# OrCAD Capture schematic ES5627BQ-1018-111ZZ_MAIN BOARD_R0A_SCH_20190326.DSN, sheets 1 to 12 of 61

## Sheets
1 P001_Revision History: rev: R0A
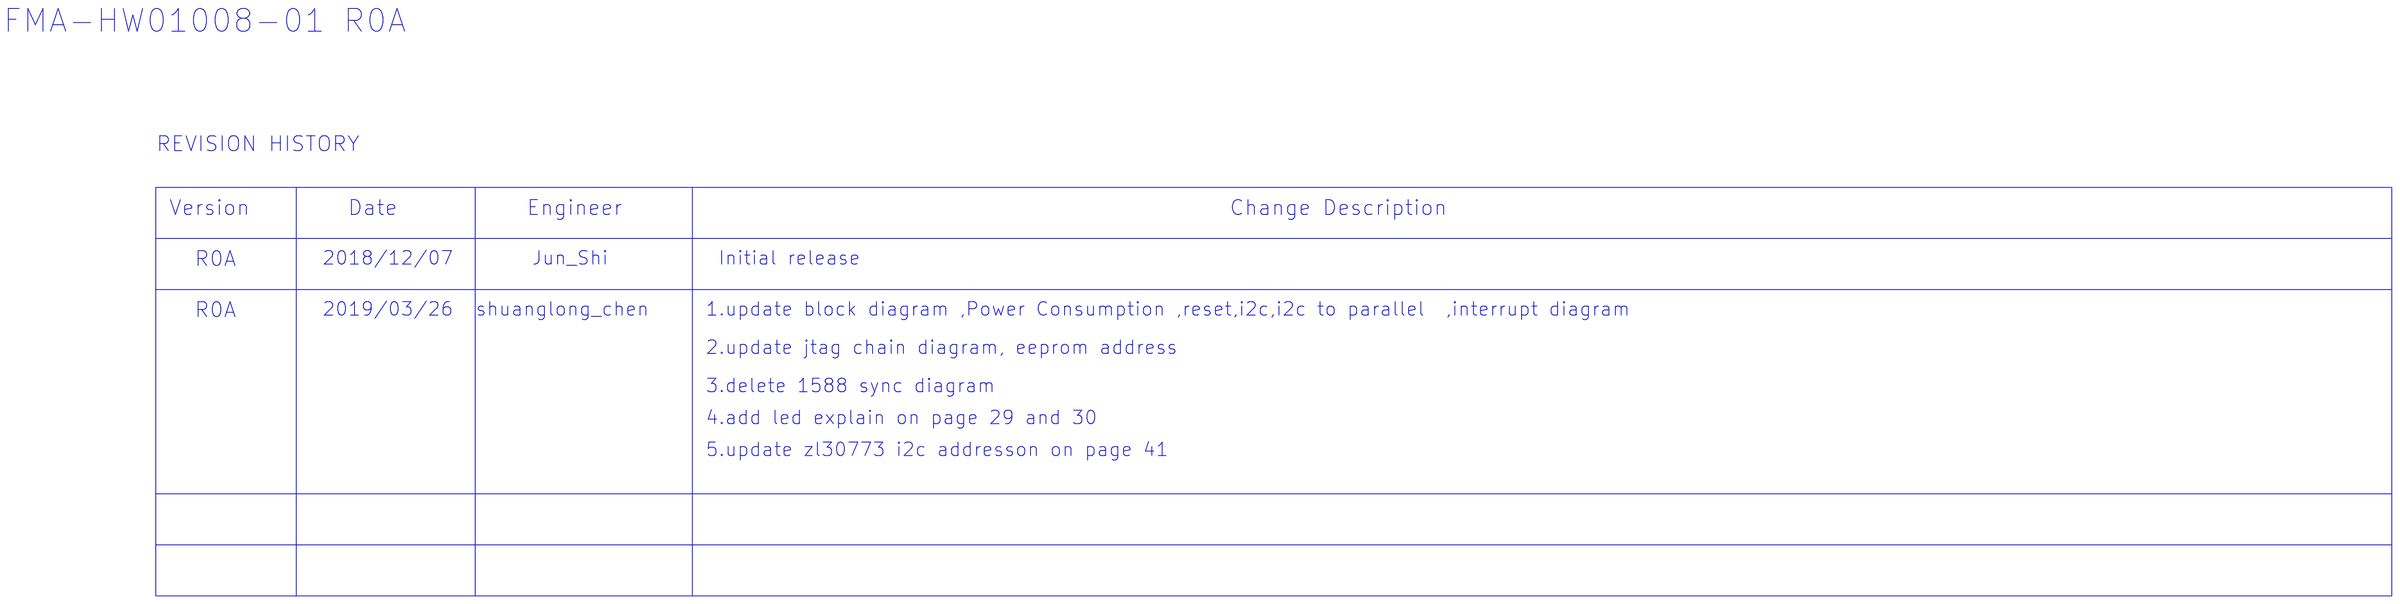
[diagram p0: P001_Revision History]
2 P002_Index List
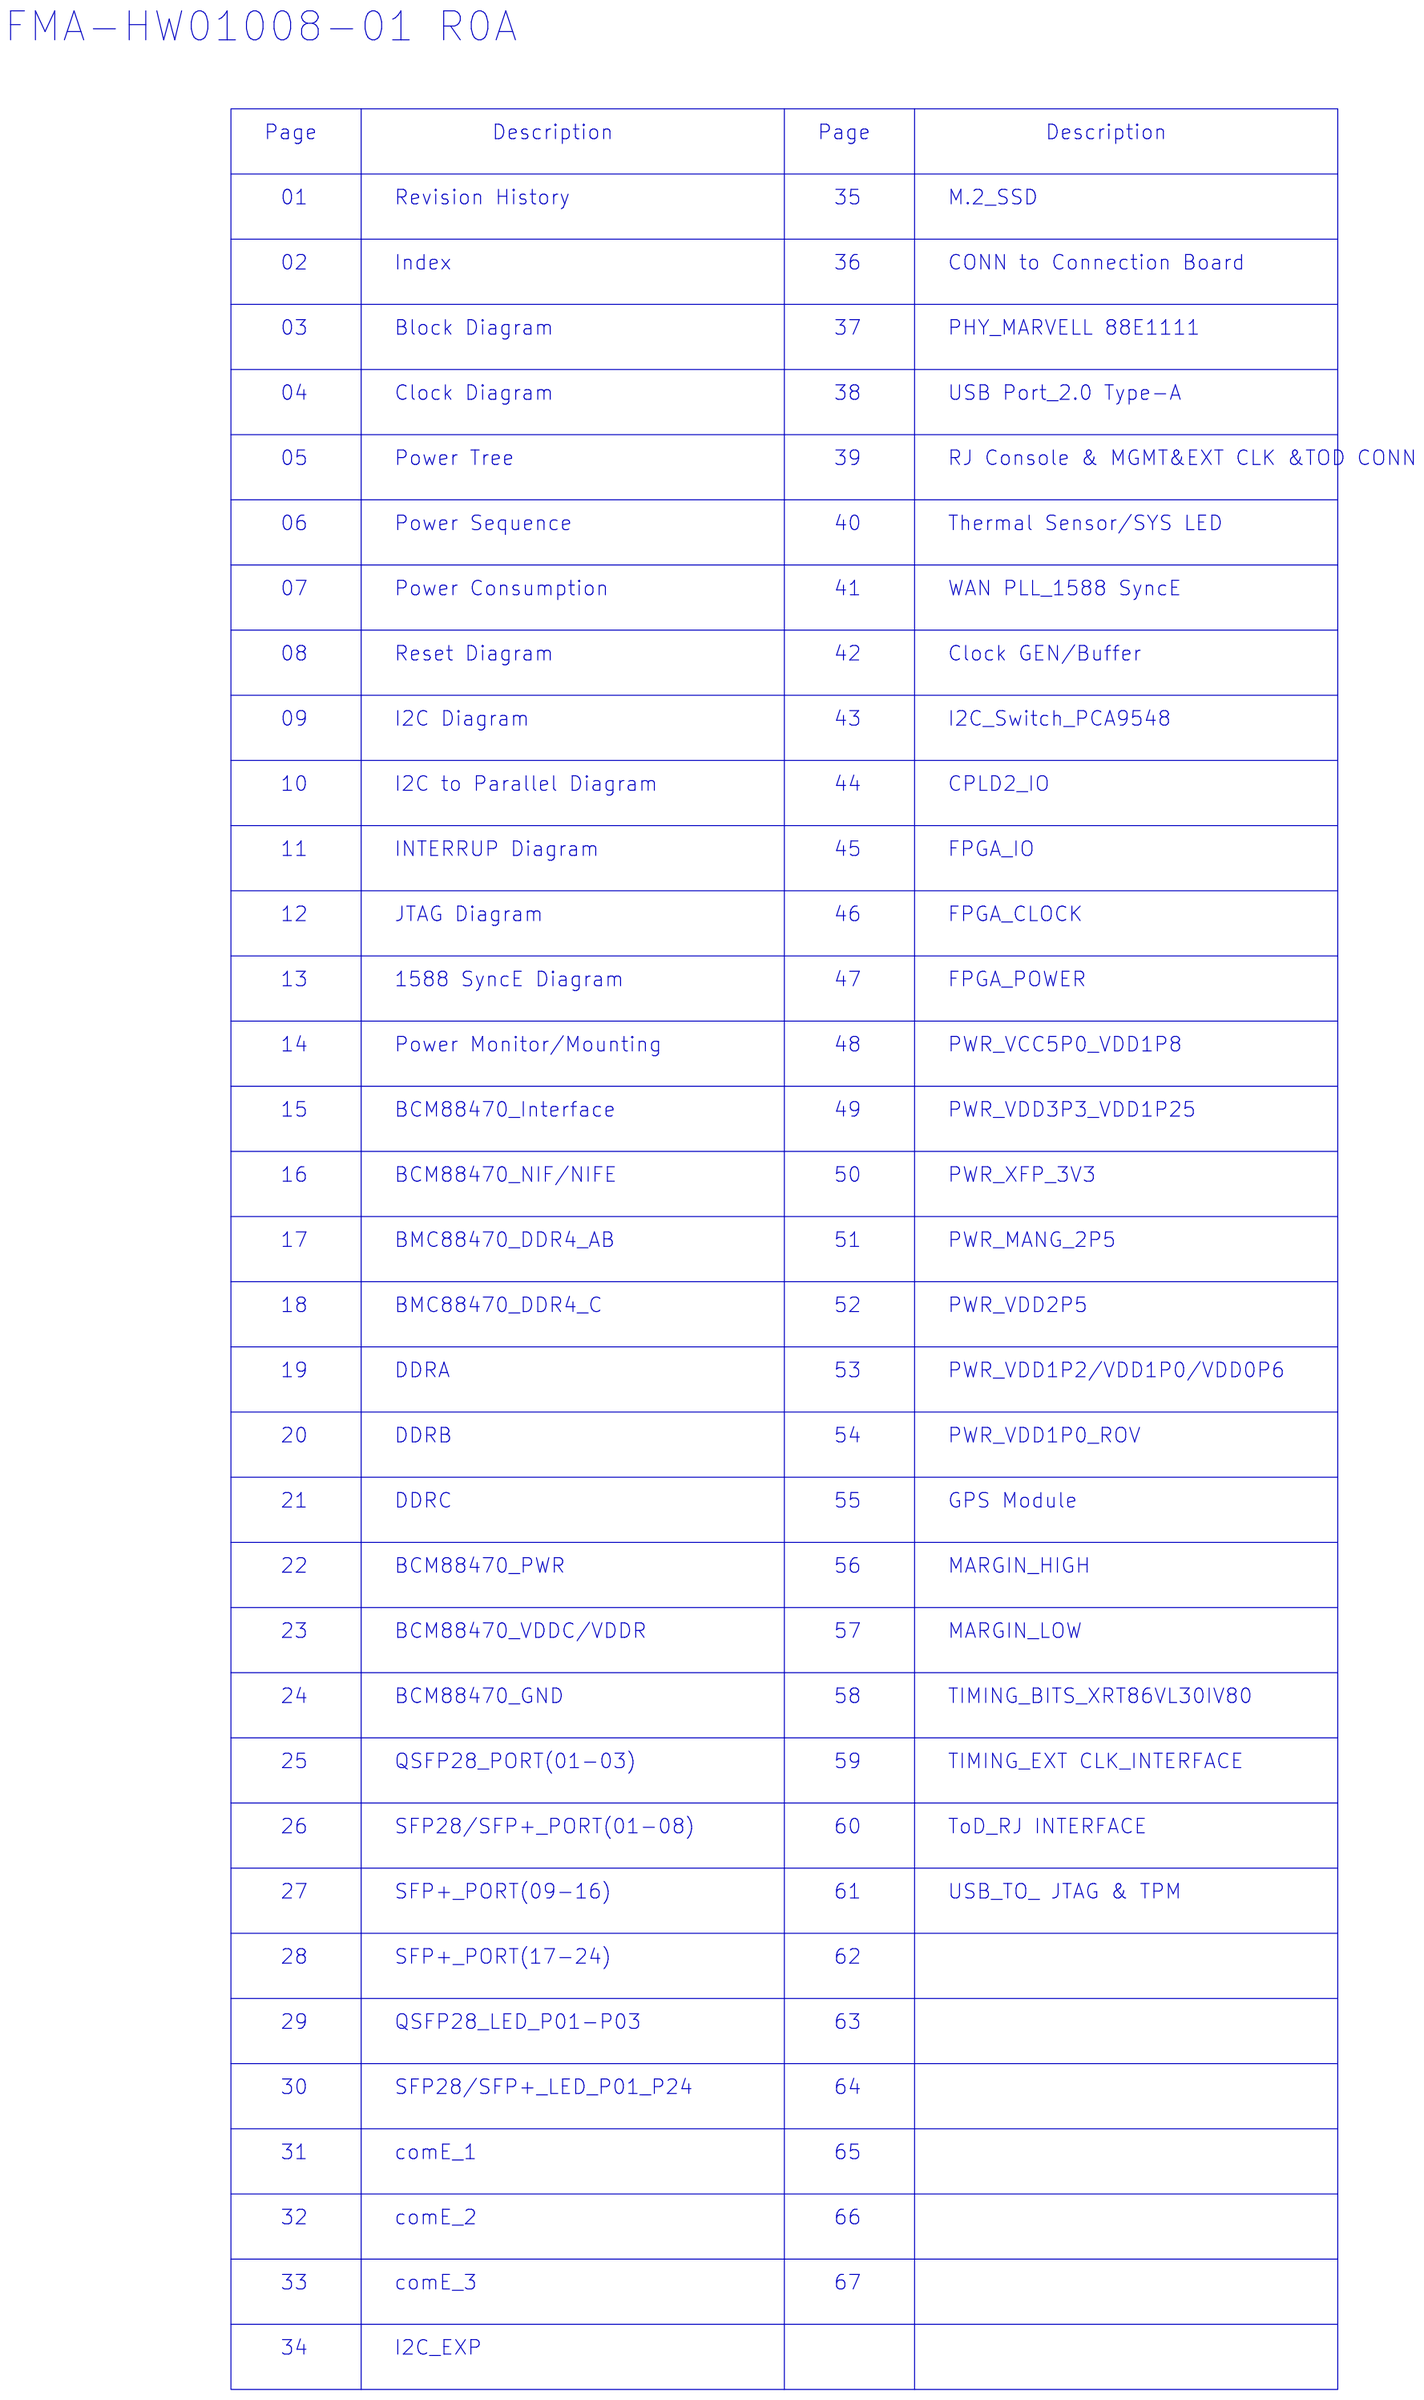
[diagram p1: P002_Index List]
3 P003_Block Diagram
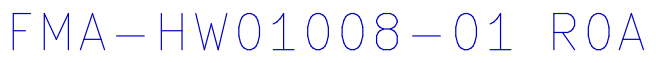
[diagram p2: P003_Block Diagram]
4 P004_Clock Diagram
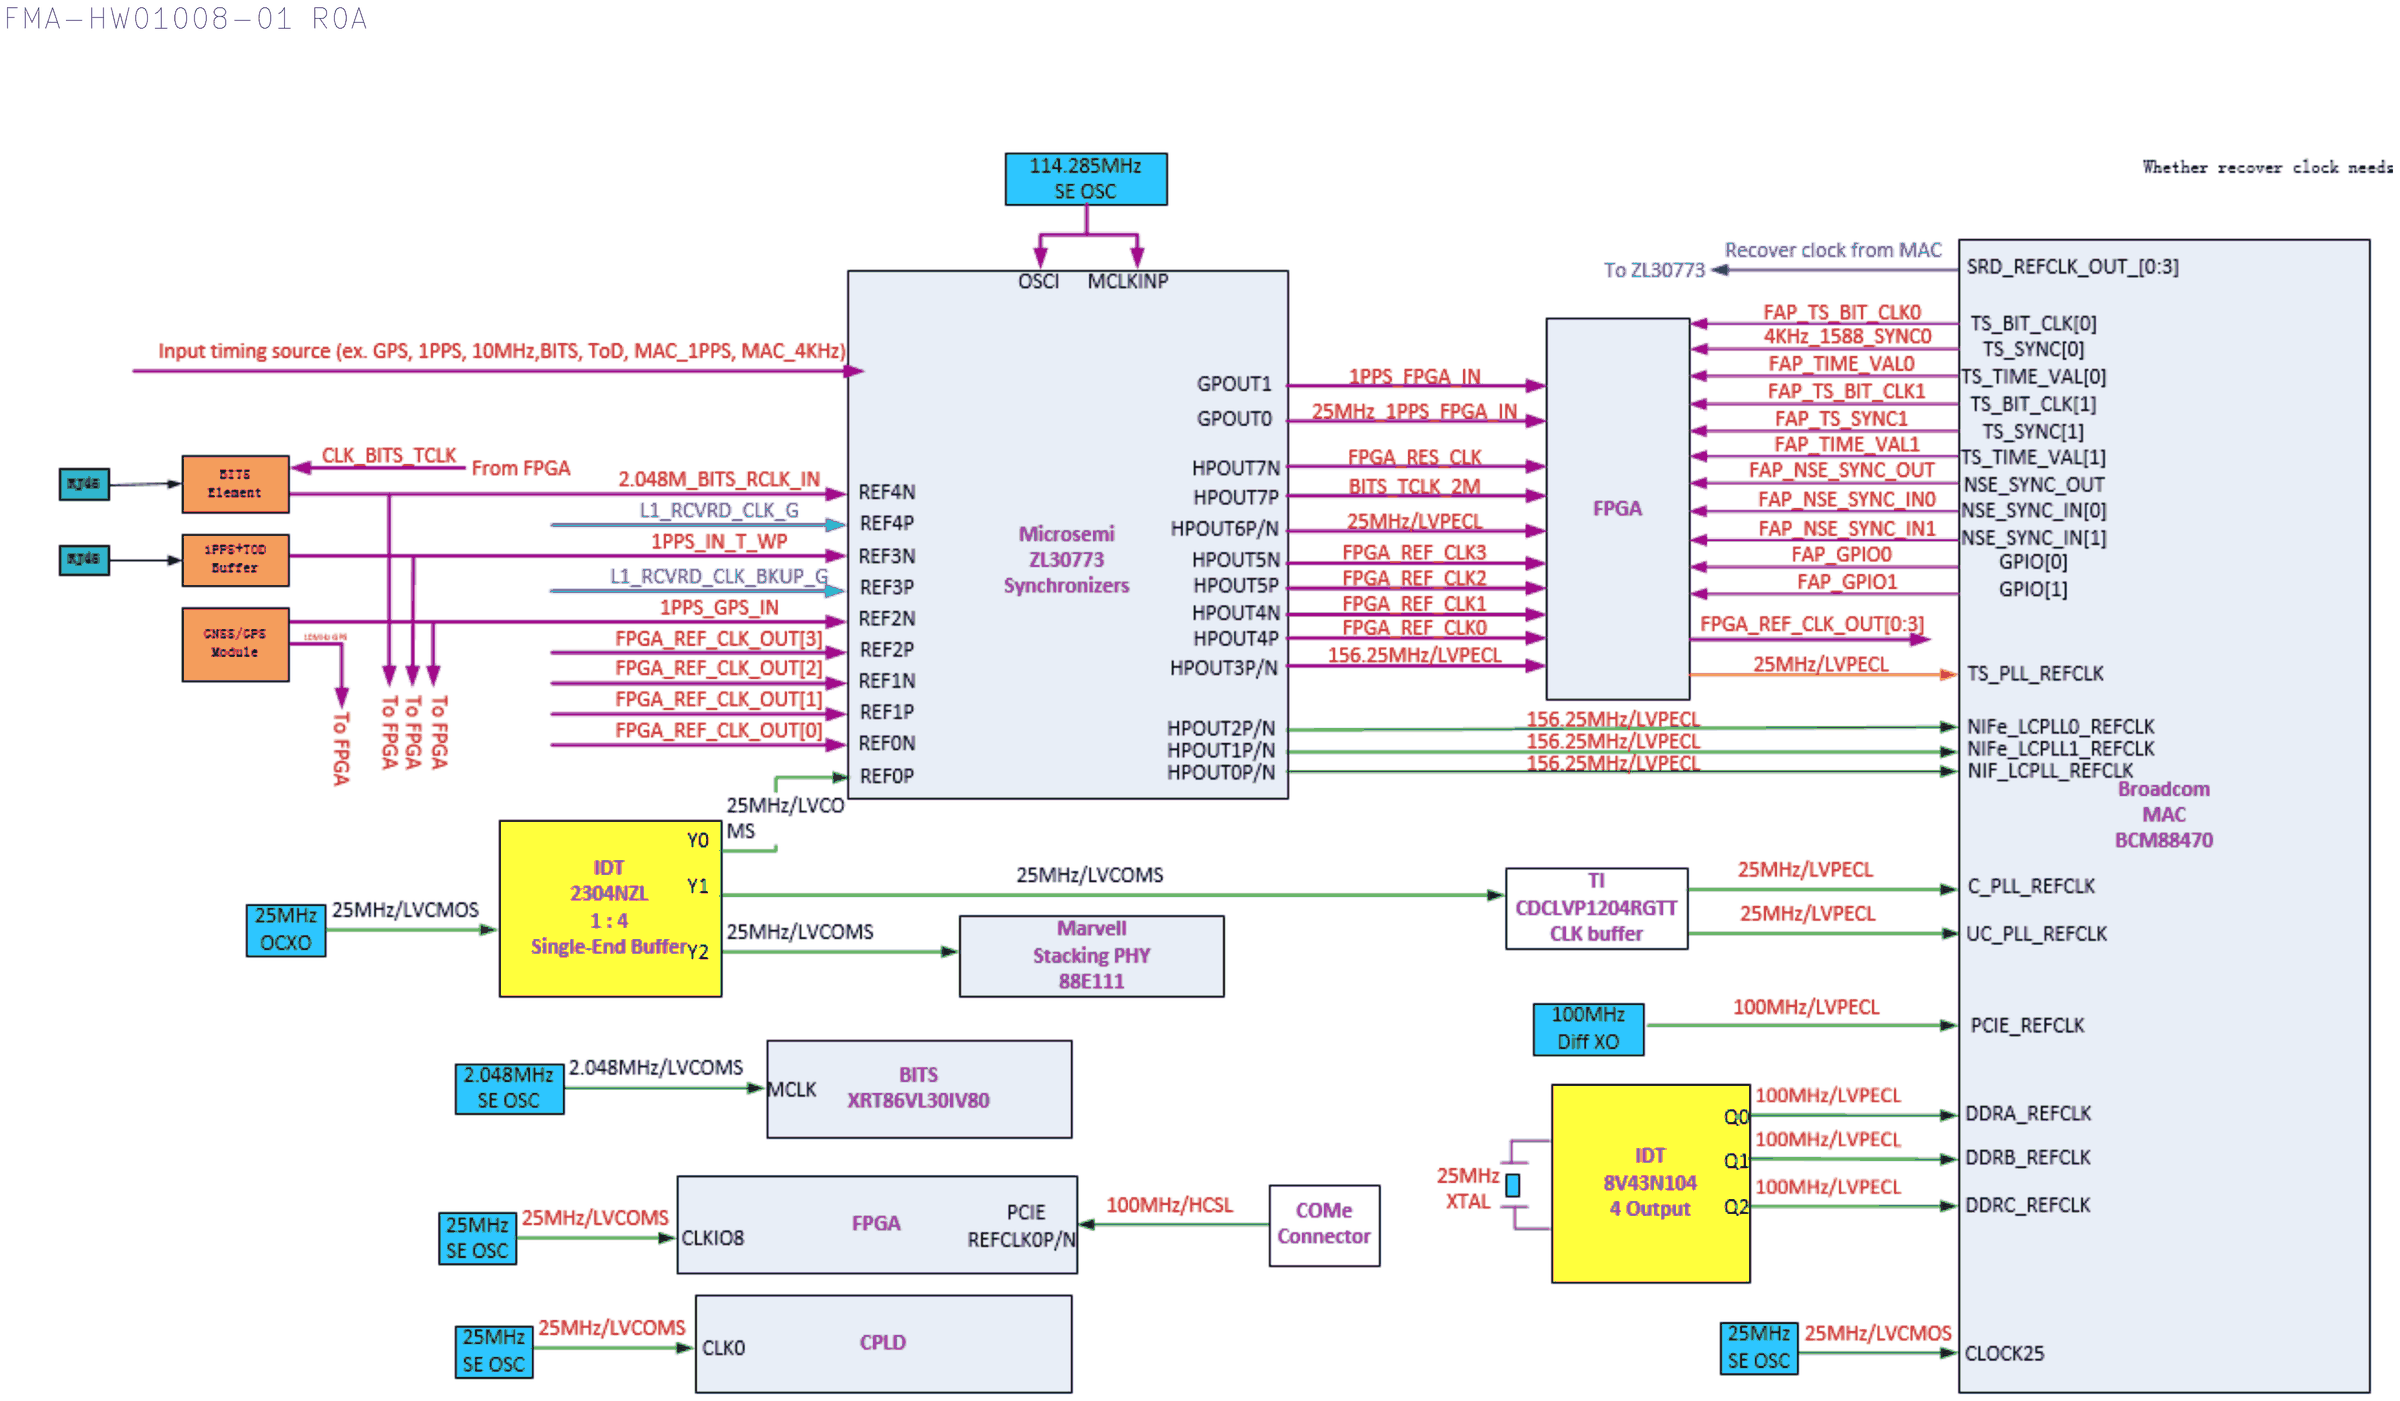
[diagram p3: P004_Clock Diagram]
5 P005_Power Tree
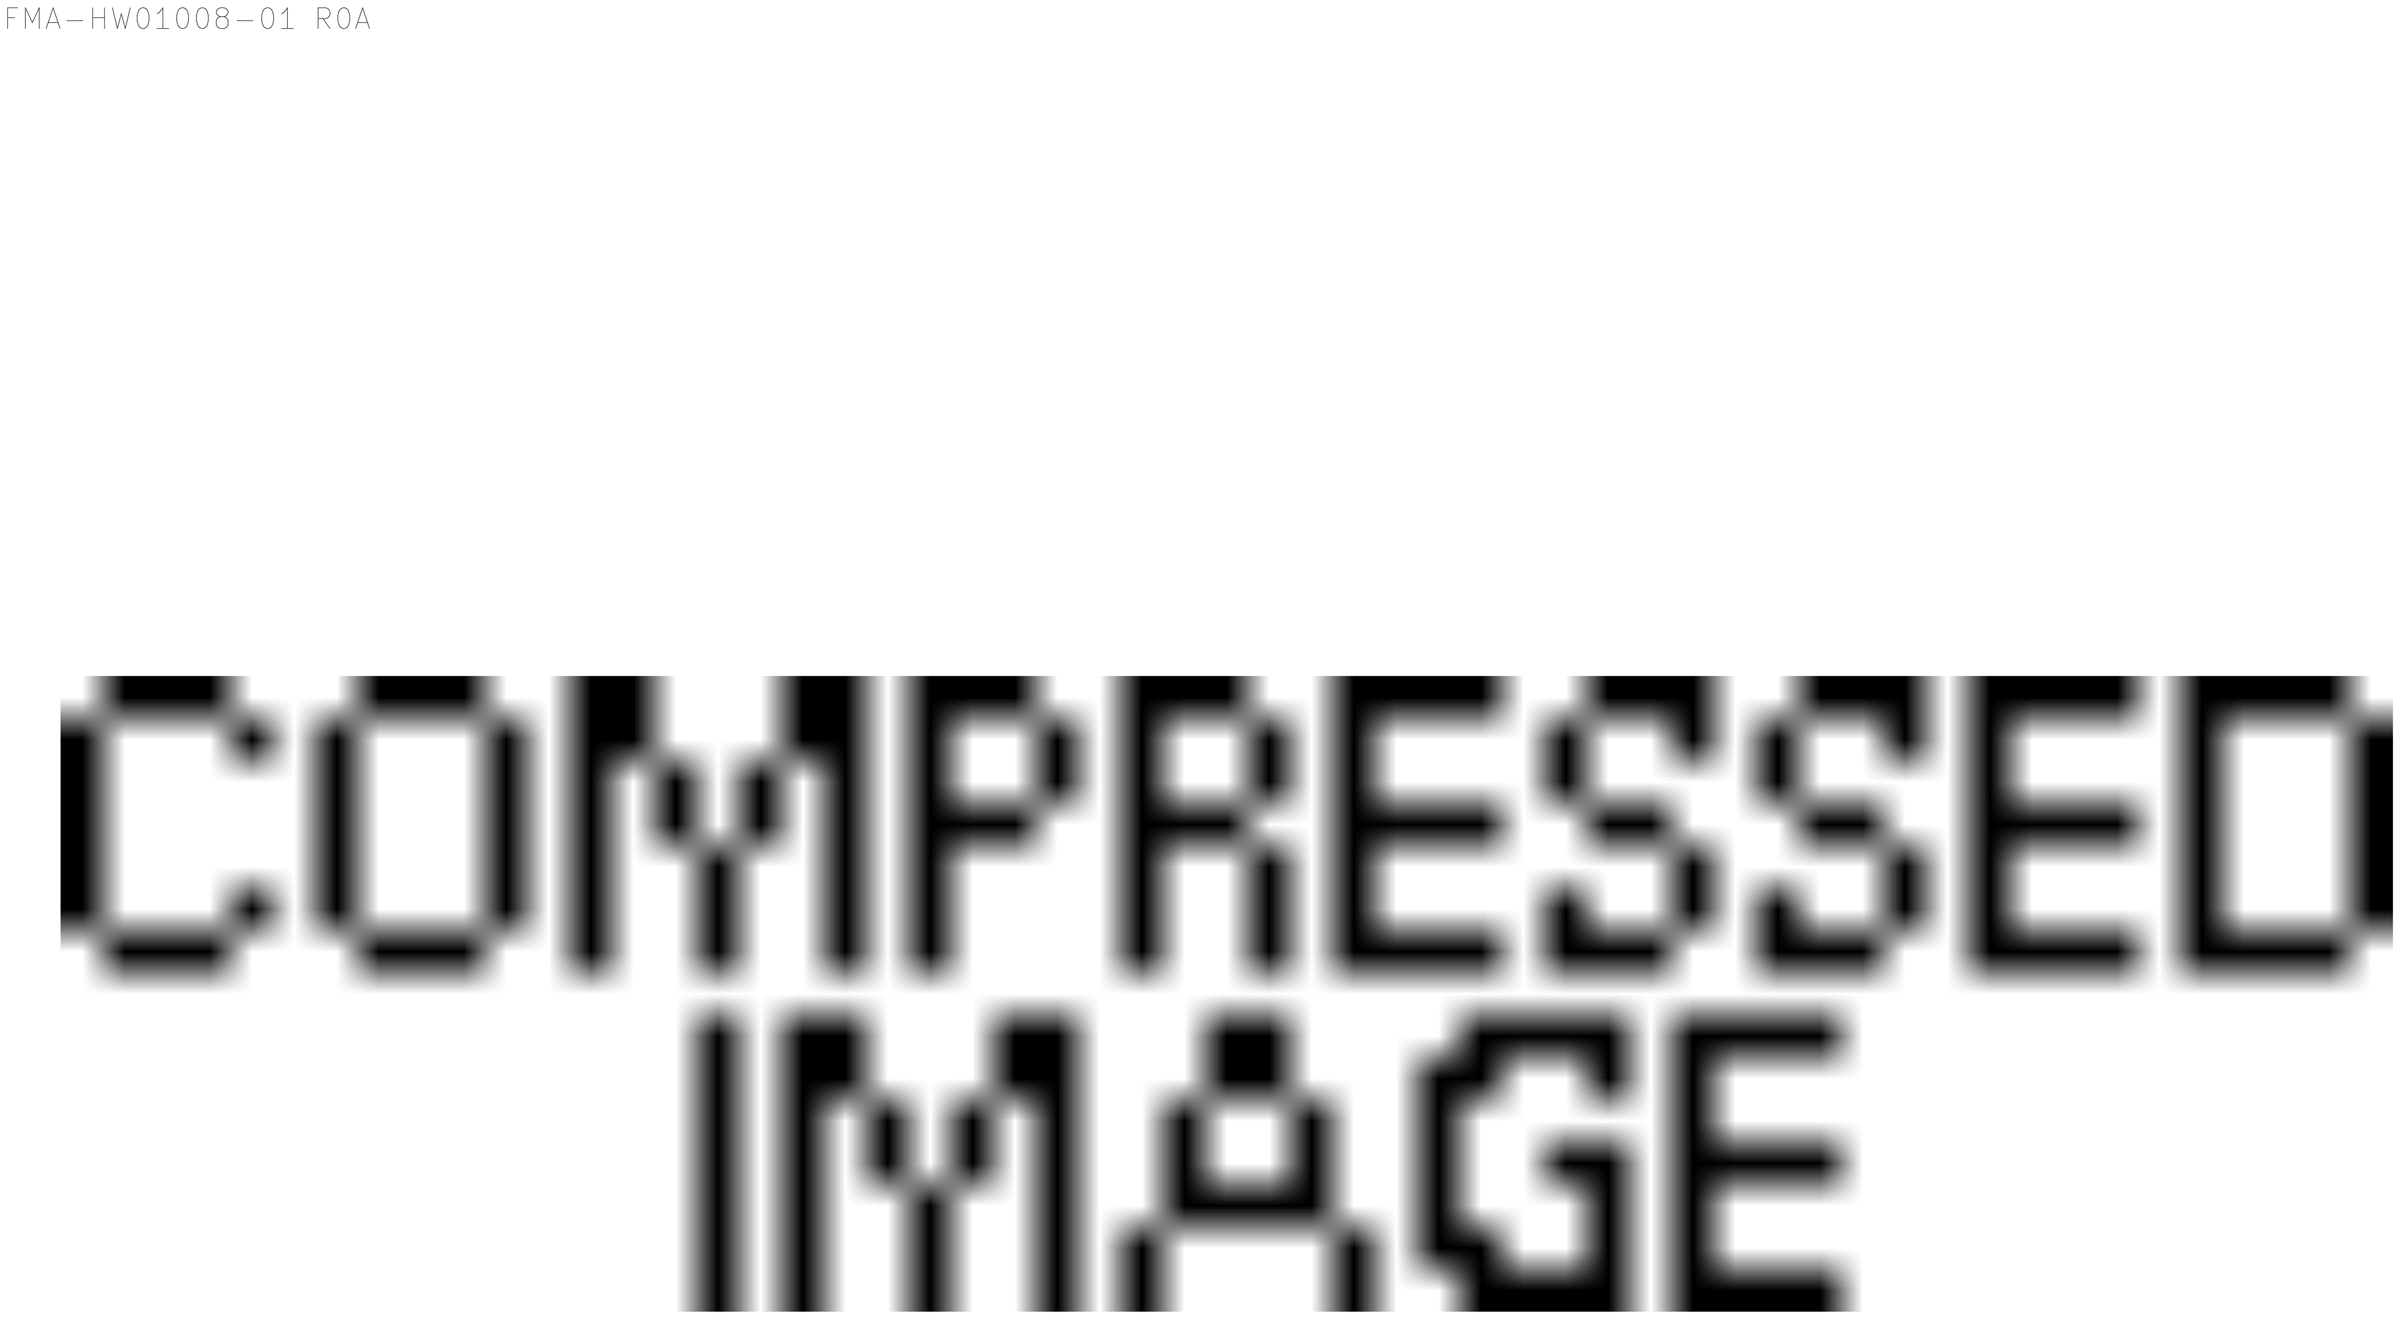
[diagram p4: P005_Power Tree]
6 P006_Power Sequence
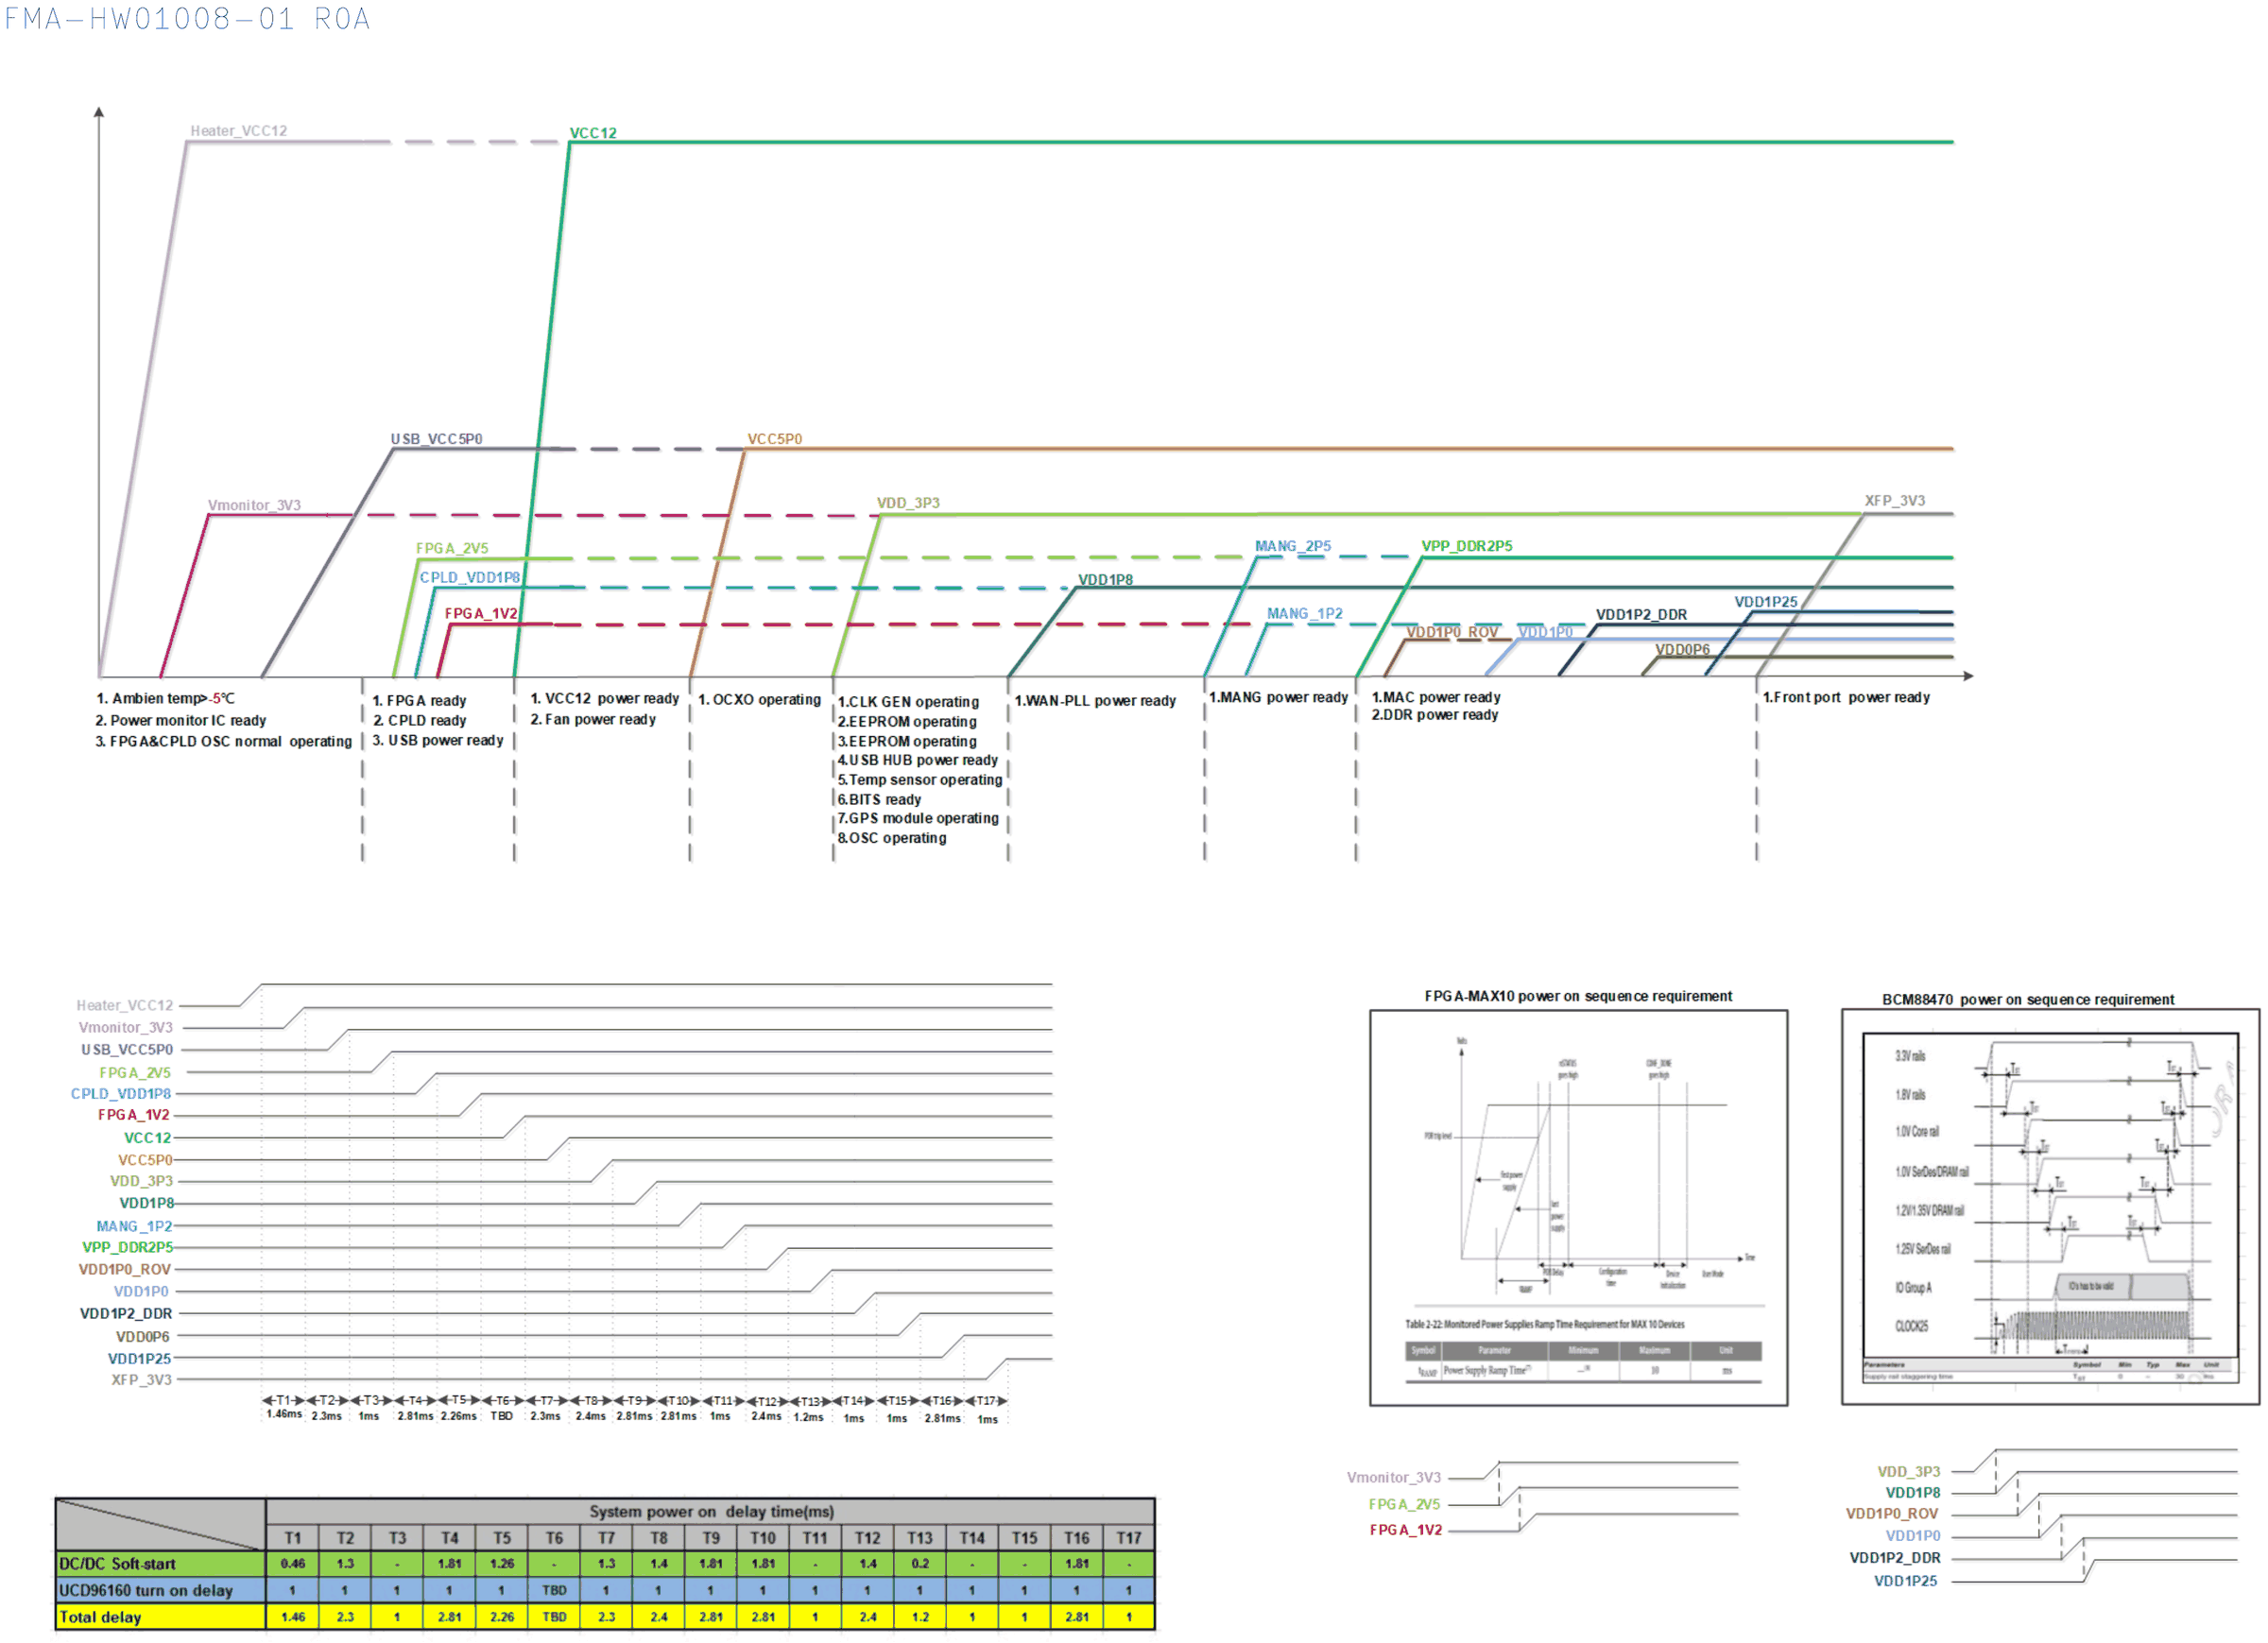
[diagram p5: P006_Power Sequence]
7 P007_Power Consumption
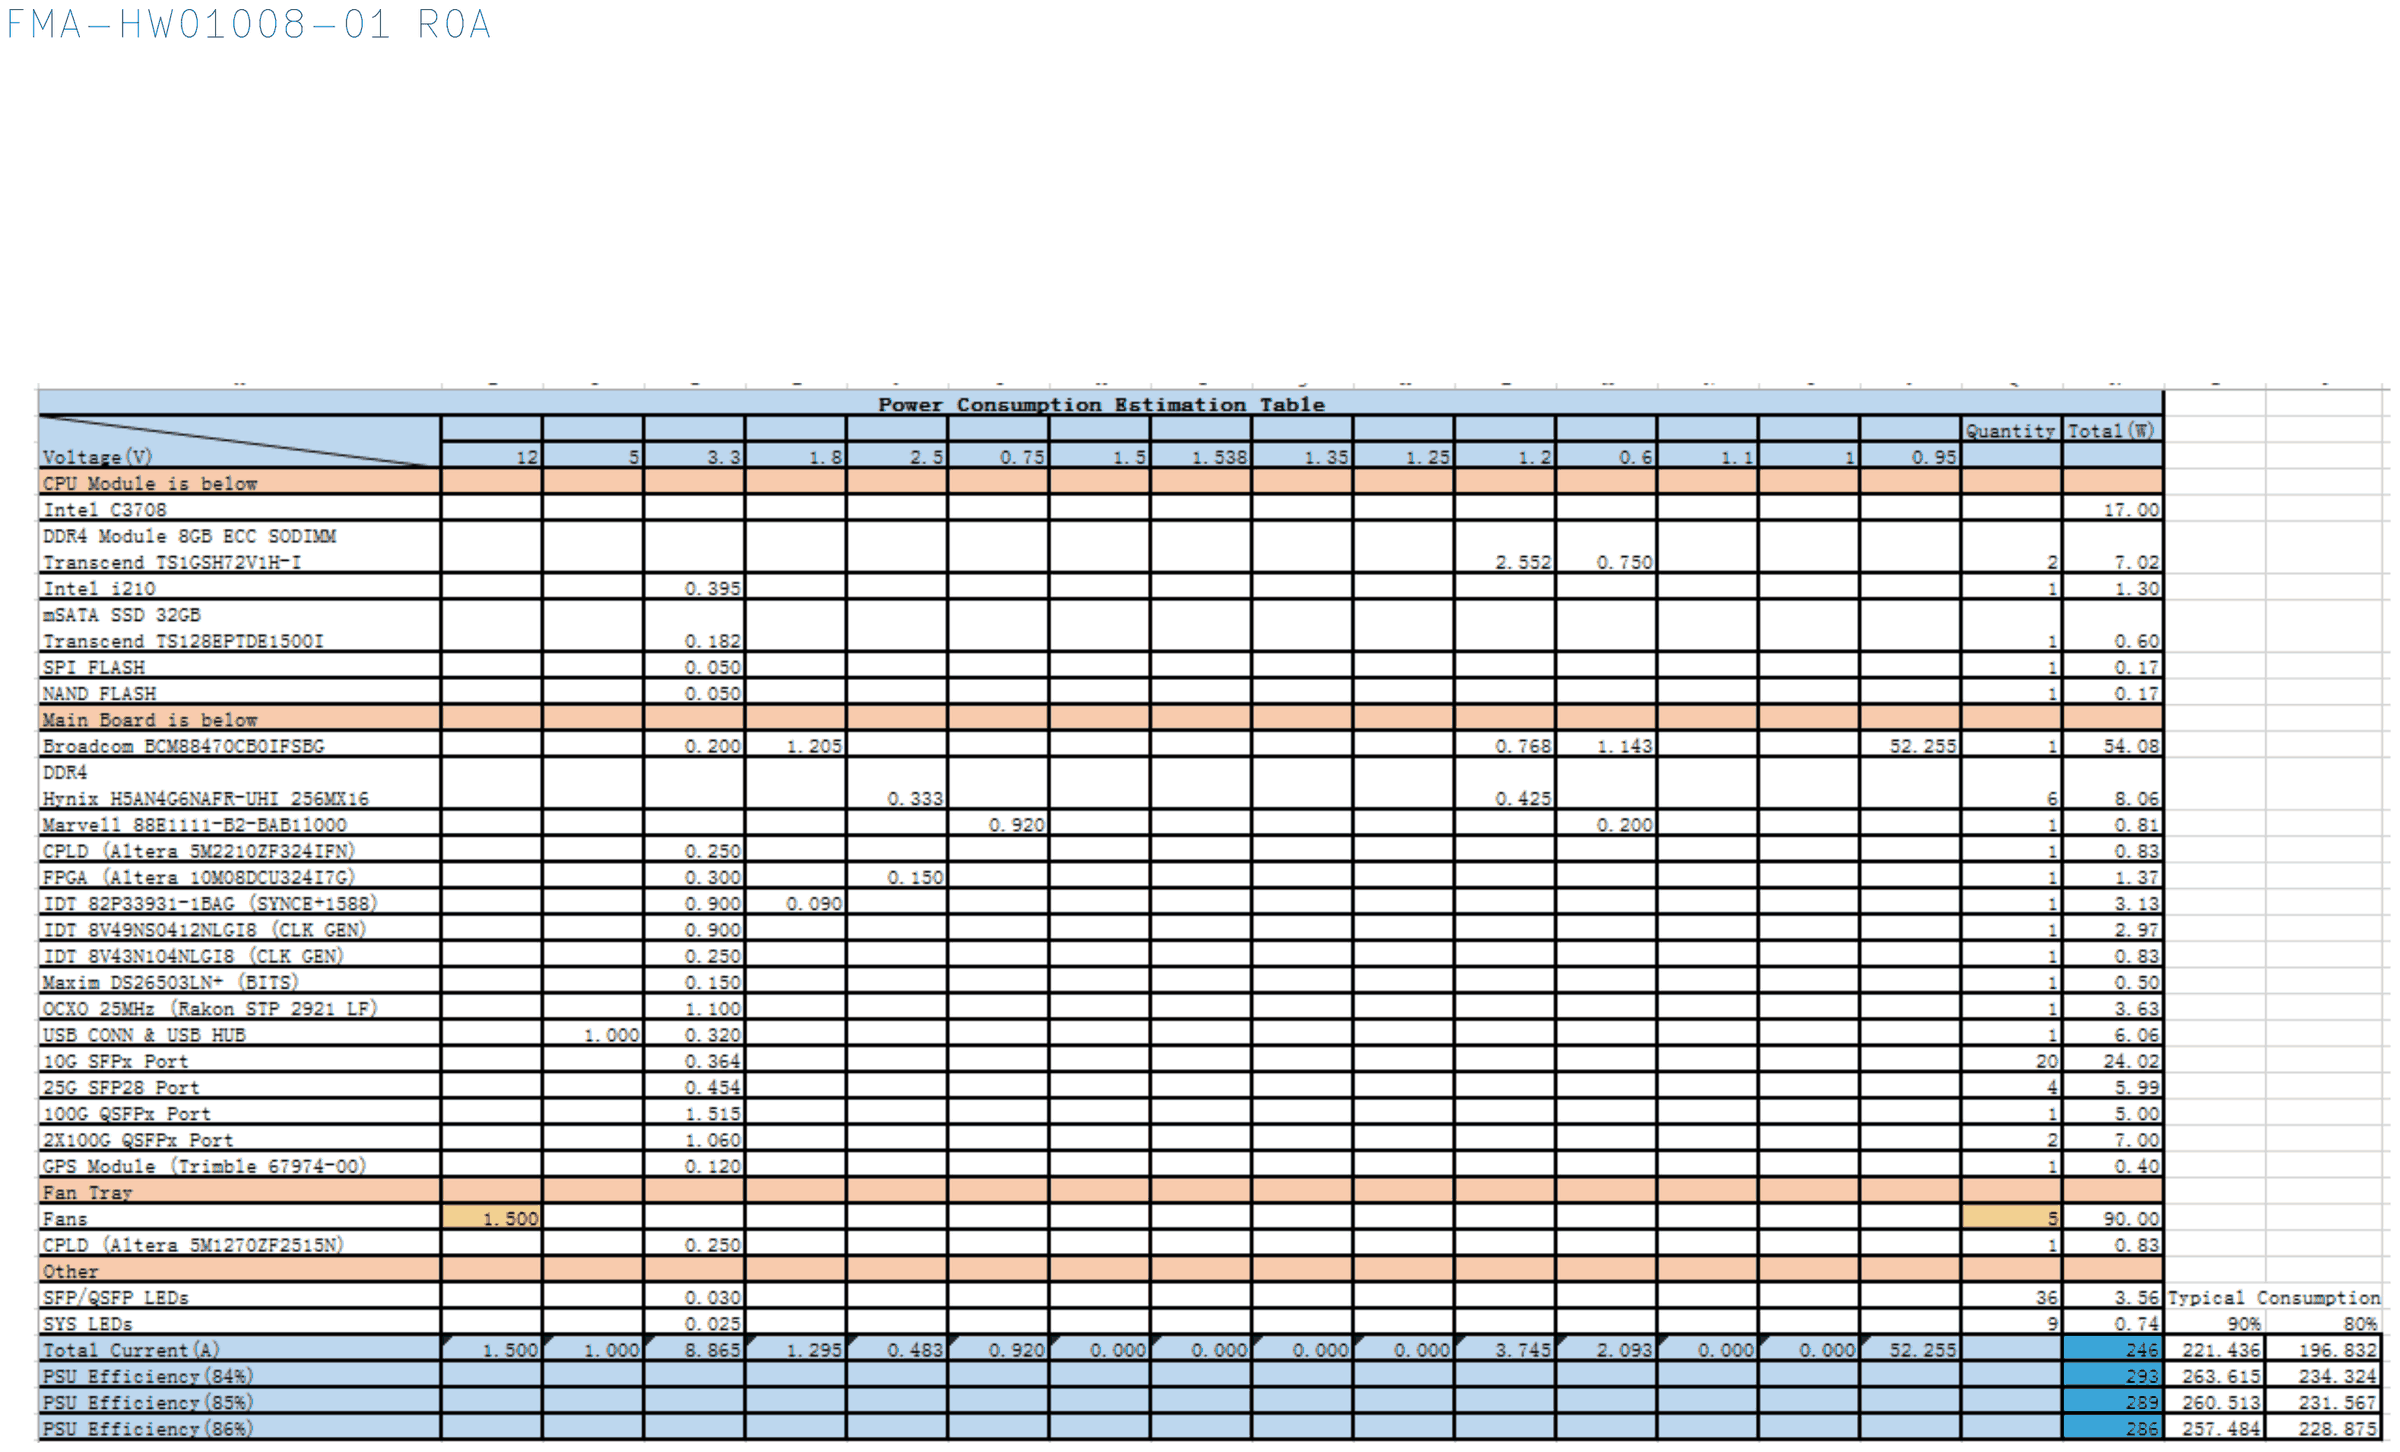
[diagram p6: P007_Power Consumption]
8 P008_Reset Diagram
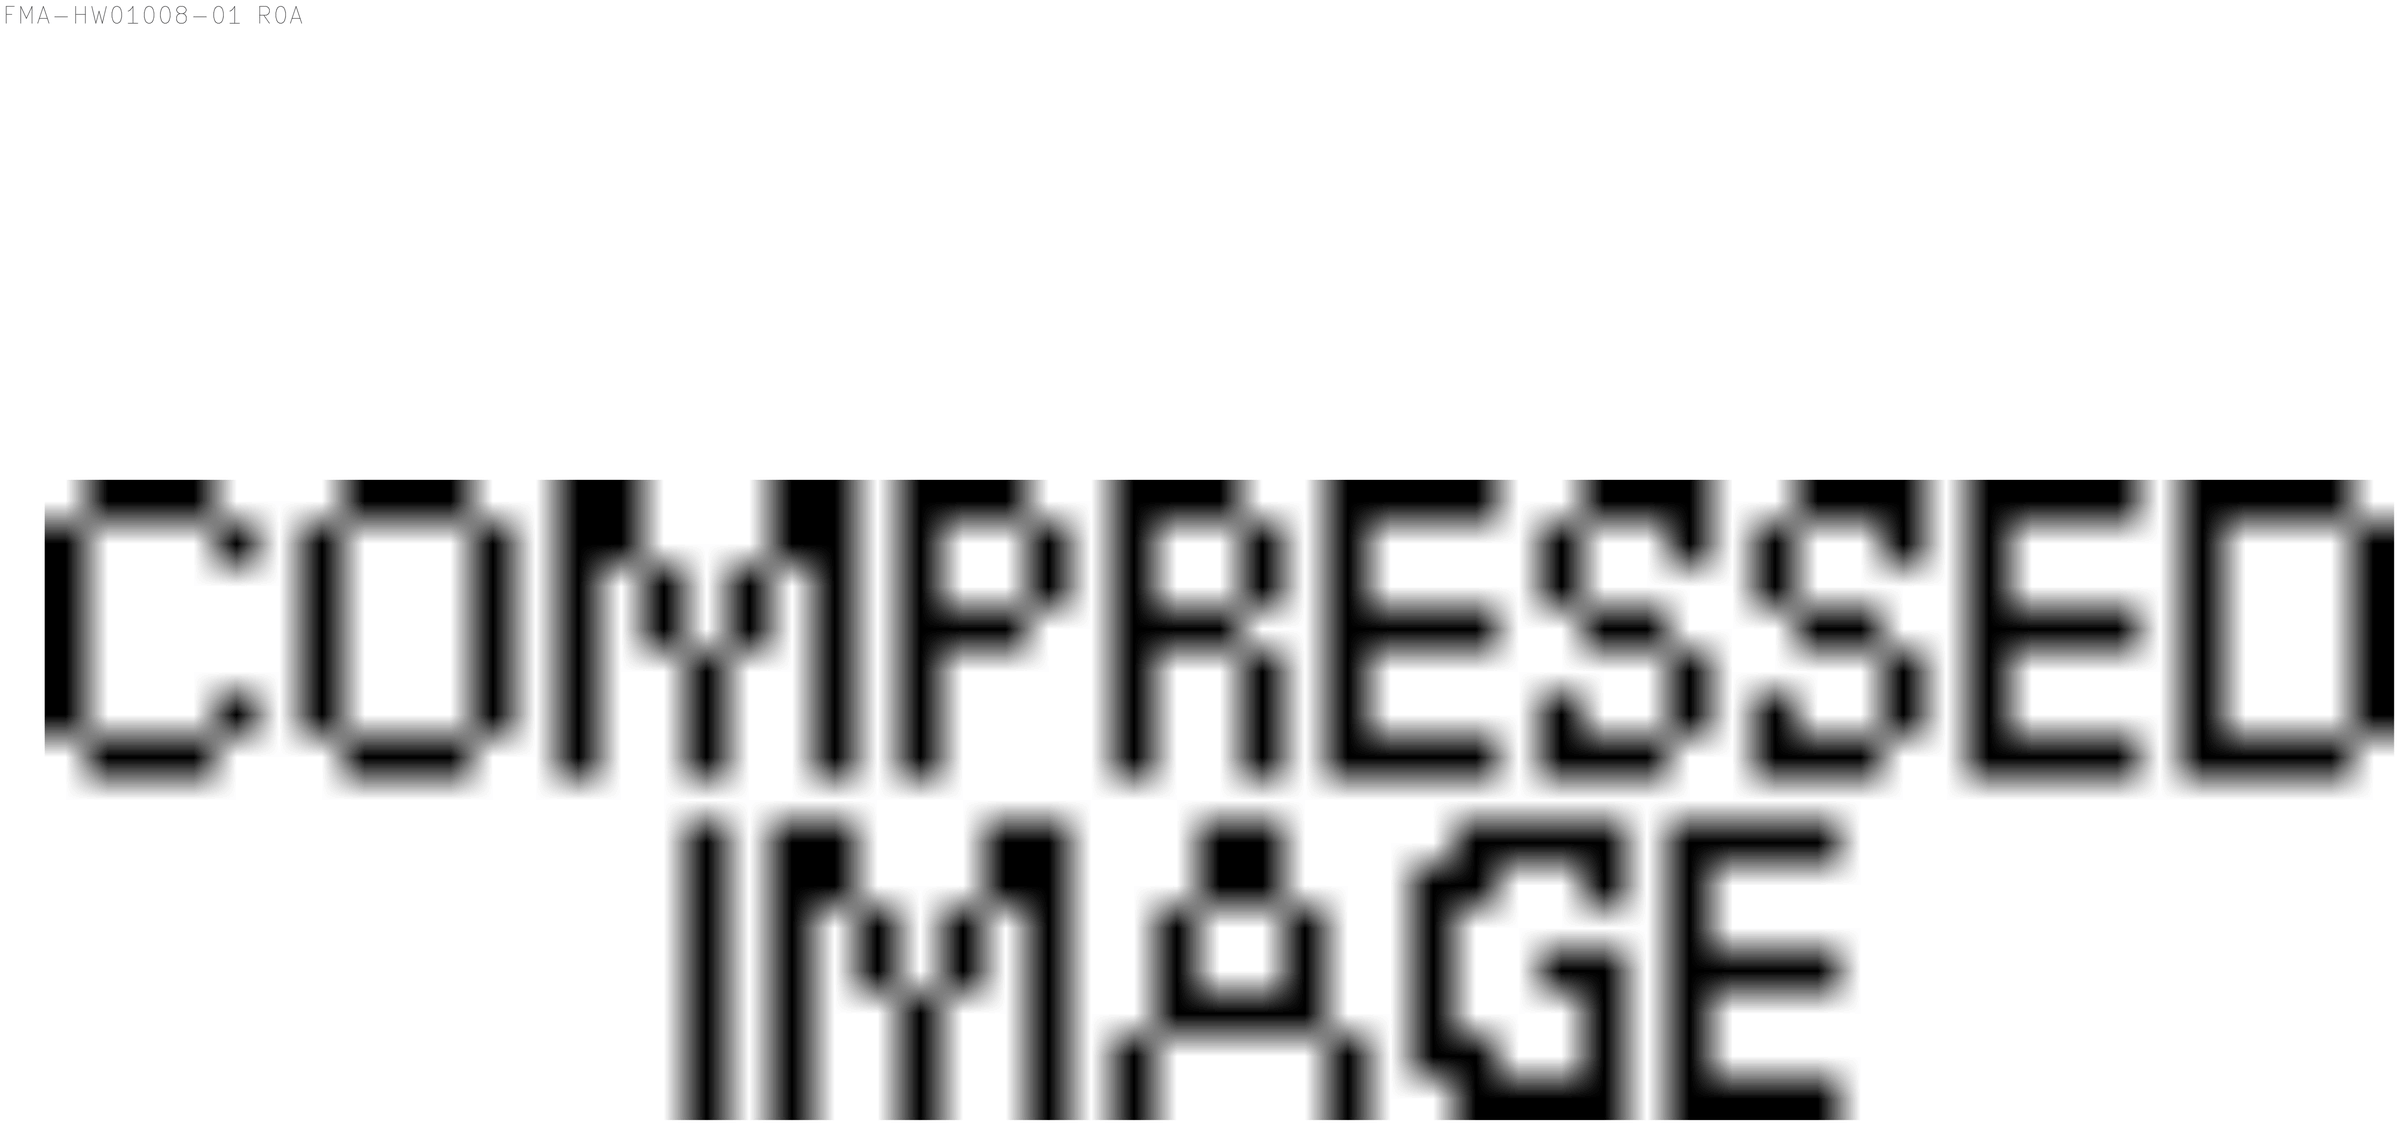
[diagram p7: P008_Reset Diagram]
9 P009_I2C Diagram
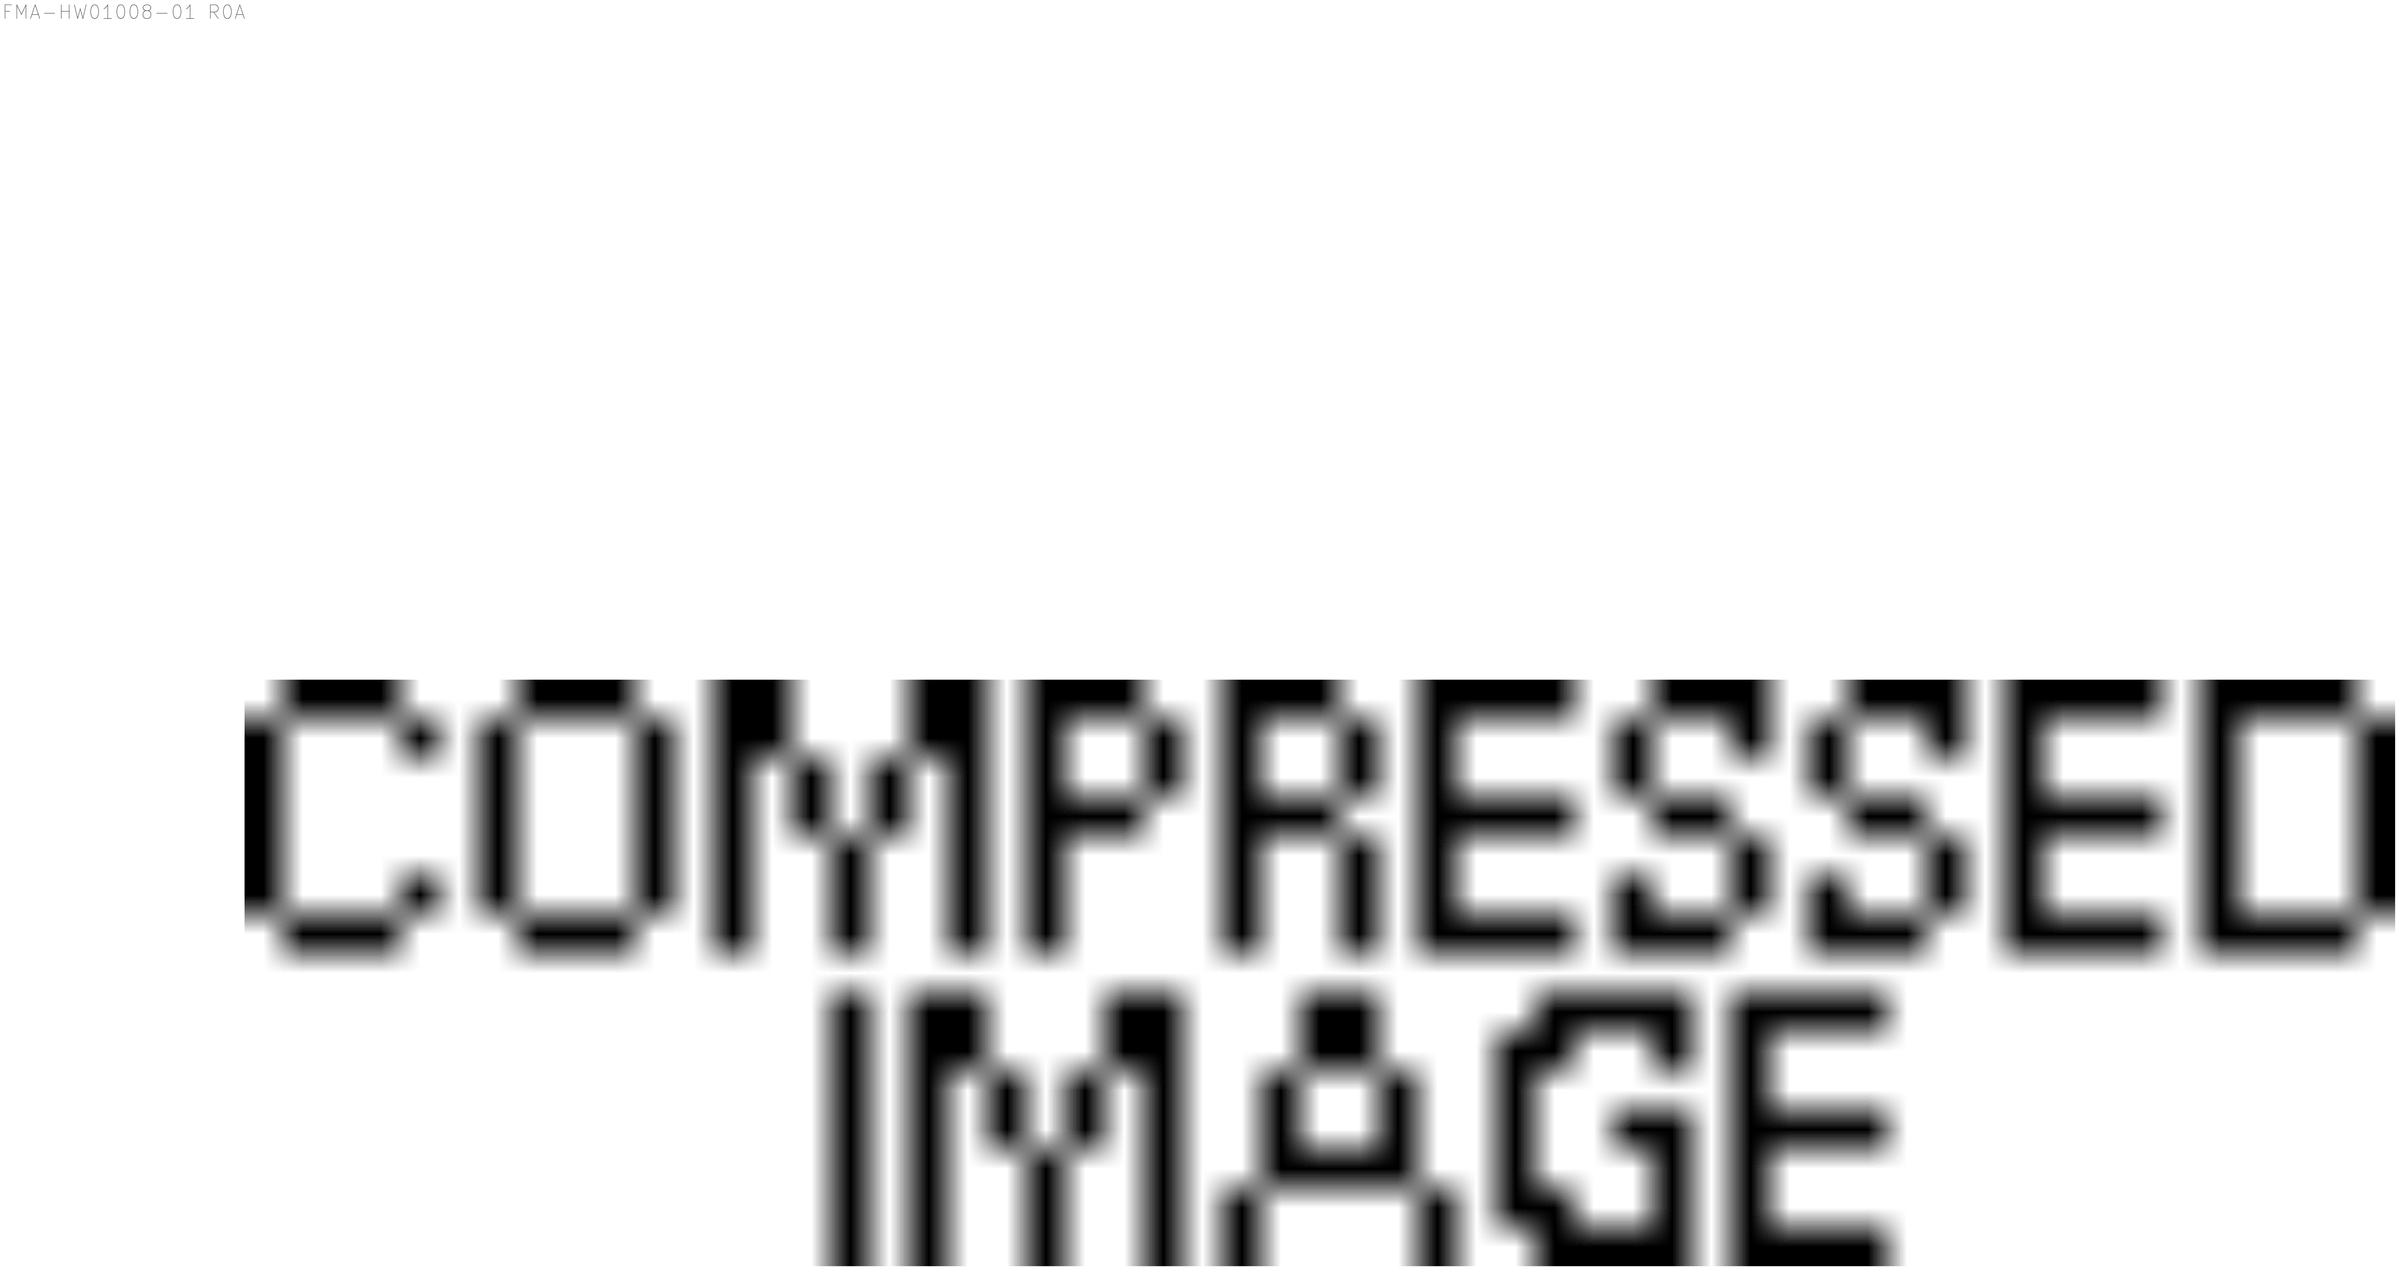
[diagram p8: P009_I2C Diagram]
10 P010_SPI Diagram
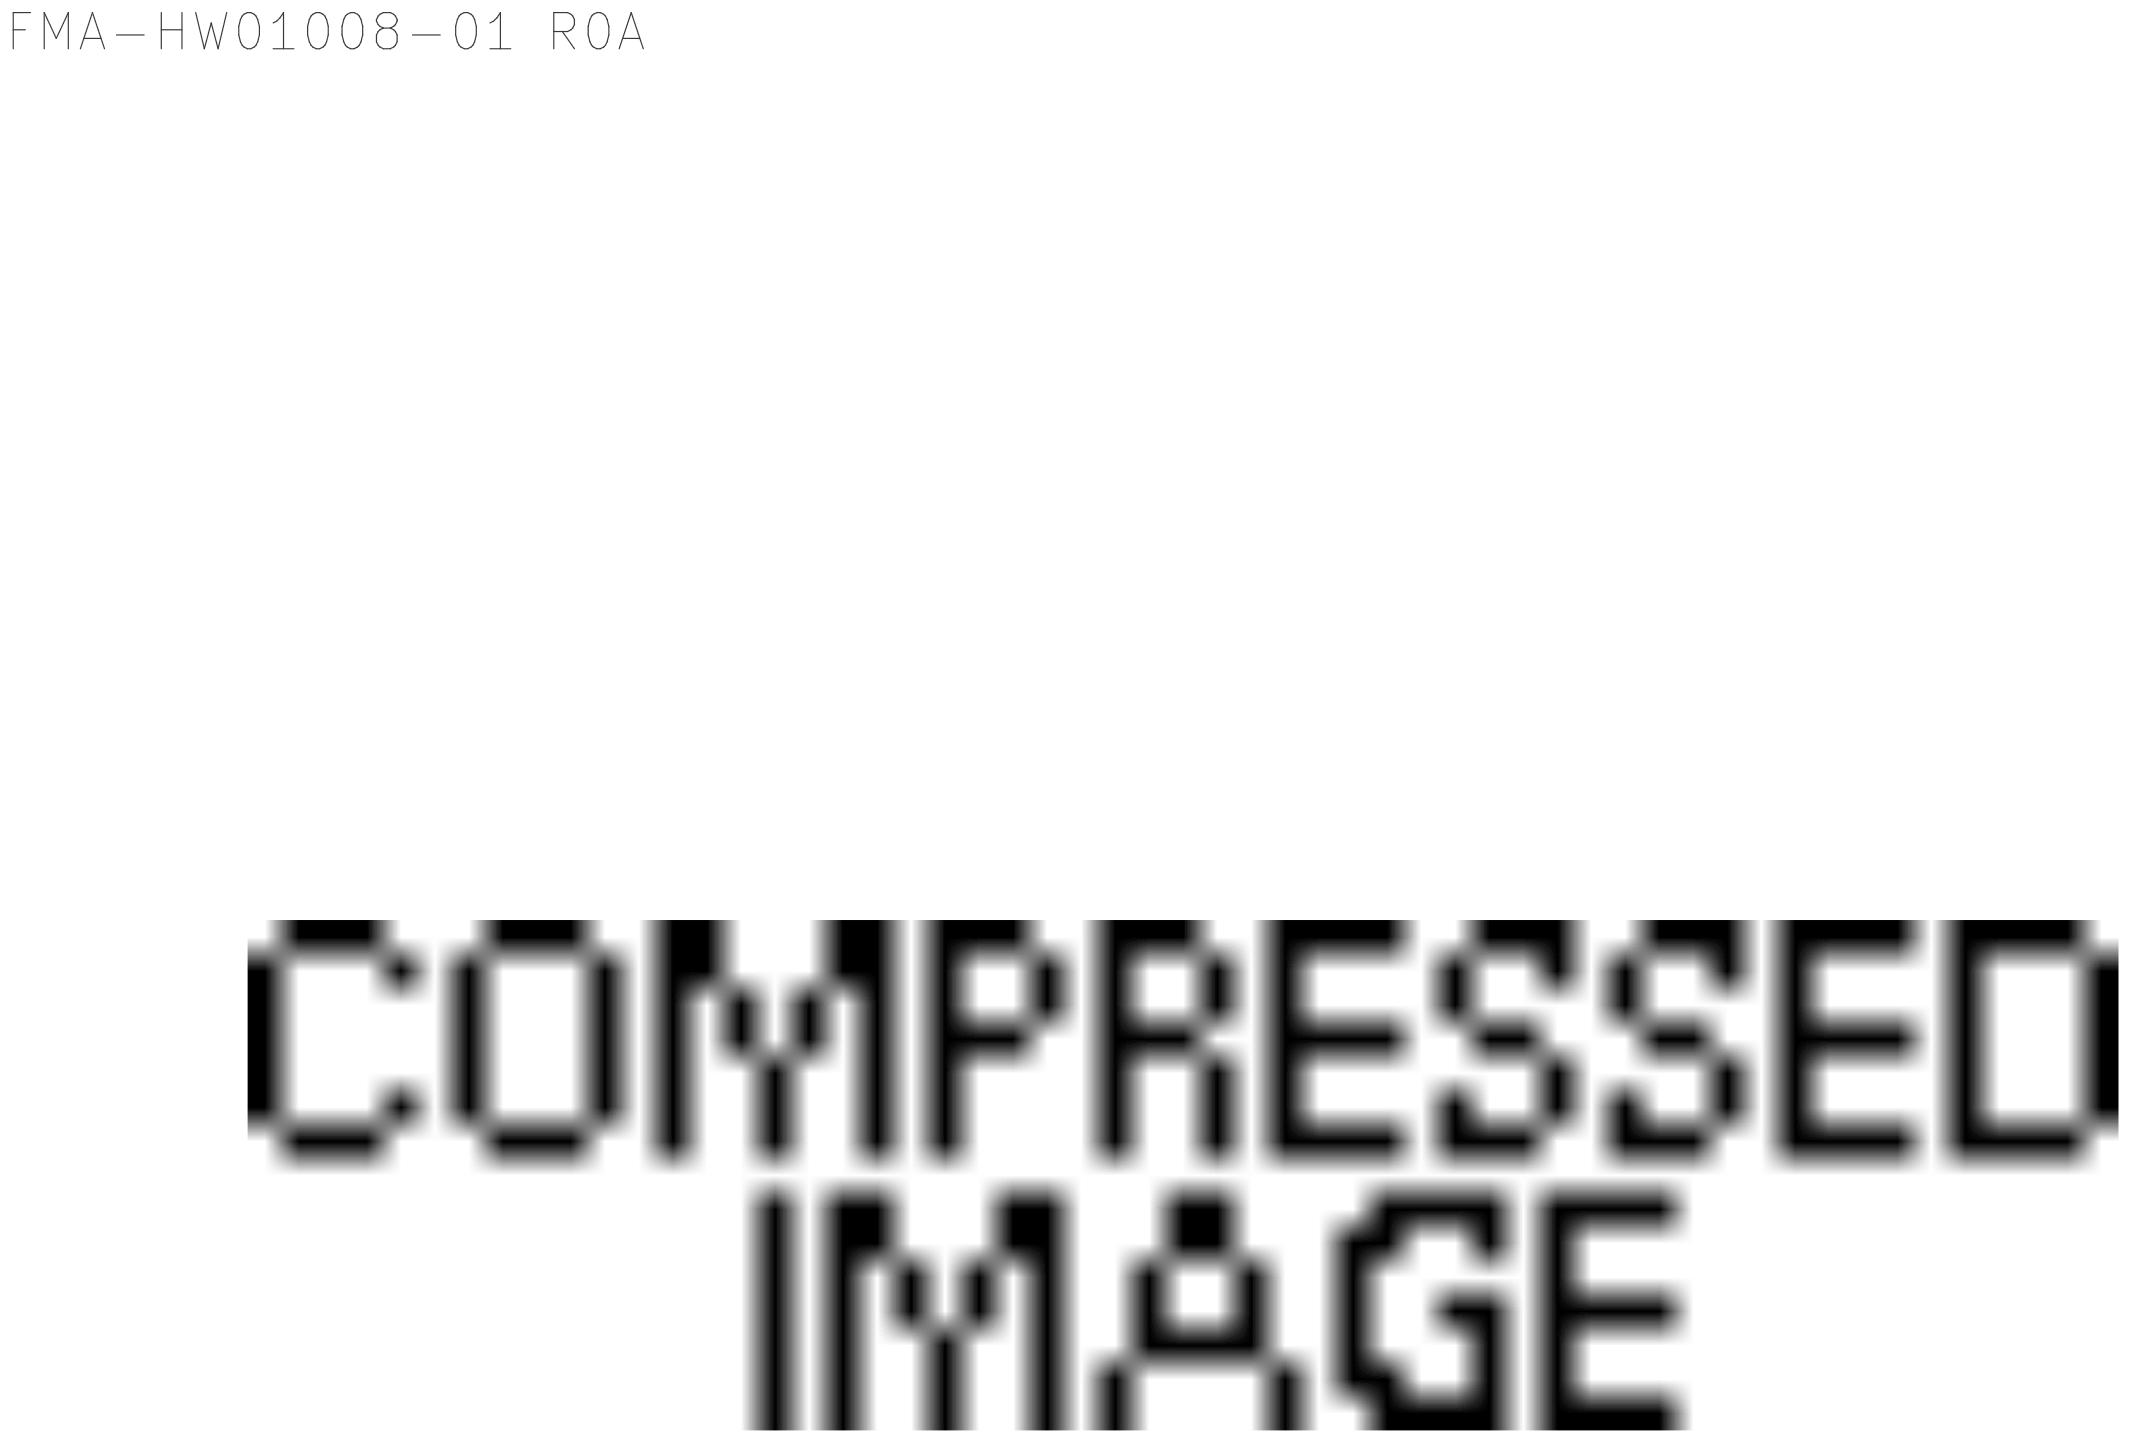
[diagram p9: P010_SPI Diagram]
11 P011_INTERRUP Diagram
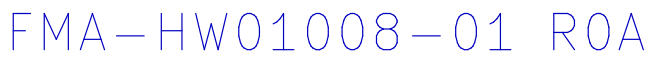
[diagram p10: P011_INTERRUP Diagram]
12 P012_JTAG Diagram
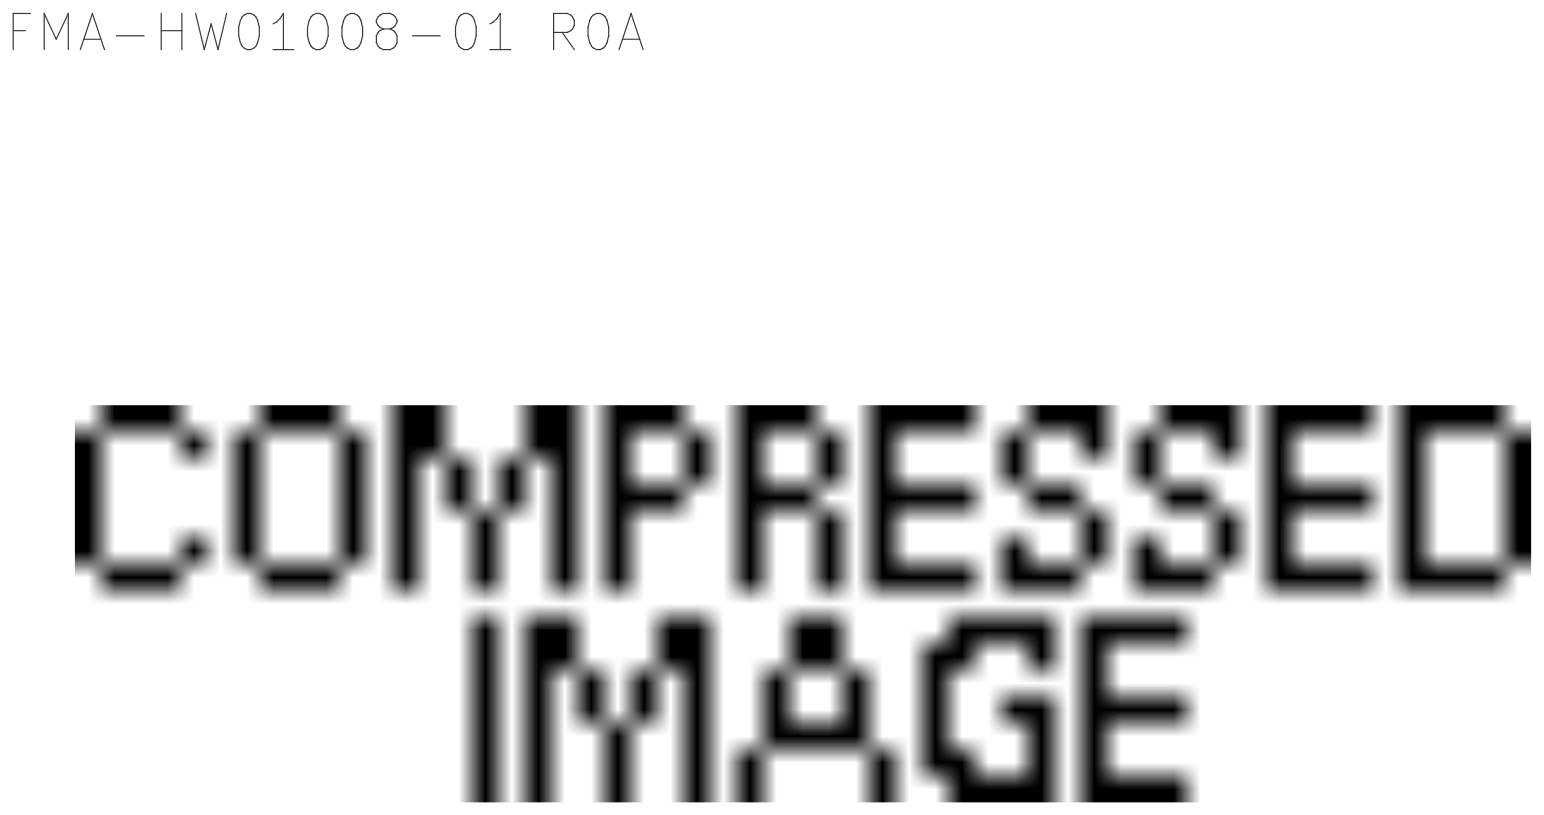
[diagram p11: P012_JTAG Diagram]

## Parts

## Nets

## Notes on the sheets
sheet 1
- FMA-HW01008-01 R0A
- REVISION HISTORY
- Version
- Date
- Engineer
- Change Description
- R0A
- 2018/12/07
- Jun_Shi
- Initial release
- R0A
- 2019/03/26
- shuanglong_chen
- 1.update block diagram ,Power Consumption ,reset,i2c,i2c to parallel  ,interrupt diagram
- 2.update jtag chain diagram, eeprom address
- 3.delete 1588 sync diagram
- 4.add led explain on page 29 and 30
- 5.update zl30773 i2c addresson on page 41
sheet 2
- FMA-HW01008-01 R0A
- Page
- Description
- Page
- Description
- 01
- Revision History
- 35
- M.2_SSD
- 02
- Index
- 36
- CONN to Connection Board
- 03
- Block Diagram
- 37
- PHY_MARVELL 88E1111
- 04
- Clock Diagram
- 38
- USB Port_2.0 Type-A
- 05
- Power Tree
- 39
- RJ Console & MGMT&EXT CLK &TOD CONN
- 06
- Power Sequence
- 40
- Thermal Sensor/SYS LED
- 07
- Power Consumption
- 41
- WAN PLL_1588 SyncE
- 08
- Reset Diagram
- 42
- Clock GEN/Buffer
- 09
- I2C Diagram
- 43
- I2C_Switch_PCA9548
- 10
- I2C to Parallel Diagram
- 44
- CPLD2_IO
- 11
- INTERRUP Diagram
- 45
- FPGA_IO
- 12
- JTAG Diagram
- 46
- FPGA_CLOCK
- 13
- 1588 SyncE Diagram
- 47
- FPGA_POWER
- 14
- Power Monitor/Mounting
- 48
- PWR_VCC5P0_VDD1P8
- 15
- BCM88470_Interface
- 49
- PWR_VDD3P3_VDD1P25
- 16
- BCM88470_NIF/NIFE
- 50
- PWR_XFP_3V3
- 17
- BMC88470_DDR4_AB
- 51
- PWR_MANG_2P5
- 18
- BMC88470_DDR4_C
- 52
- PWR_VDD2P5
- 19
- DDRA
- 53
- PWR_VDD1P2/VDD1P0/VDD0P6
- 20
- DDRB
- 54
- PWR_VDD1P0_ROV
- 21
- DDRC
- 55
- GPS Module
- 22
- BCM88470_PWR
- 56
- MARGIN_HIGH
- 23
- BCM88470_VDDC/VDDR
- 57
- MARGIN_LOW
- 24
- BCM88470_GND
- 58
- TIMING_BITS_XRT86VL30IV80
- 25
- QSFP28_PORT(01-03)
- 59
- TIMING_EXT CLK_INTERFACE
- 26
- SFP28/SFP+_PORT(01-08)
- 60
- ToD_RJ INTERFACE
- 27
- SFP+_PORT(09-16)
- 61
- USB_TO_ JTAG & TPM
- 28
- SFP+_PORT(17-24)
- 62
- 29
- QSFP28_LED_P01-P03
- 63
- 30
- SFP28/SFP+_LED_P01_P24
- 64
- 31
- comE_1
- 65
- 32
- comE_2
- 66
- 33
- comE_3
- 67
- 34
- I2C_EXP
sheet 3
- FMA-HW01008-01 R0A
sheet 4
- FMA-HW01008-01 R0A
sheet 5
- FMA-HW01008-01 R0A
sheet 6
- FMA-HW01008-01 R0A
sheet 7
- FMA-HW01008-01 R0A
sheet 8
- FMA-HW01008-01 R0A
sheet 9
- FMA-HW01008-01 R0A
sheet 10
- FMA-HW01008-01 R0A
sheet 11
- FMA-HW01008-01 R0A
sheet 12
- FMA-HW01008-01 R0A
